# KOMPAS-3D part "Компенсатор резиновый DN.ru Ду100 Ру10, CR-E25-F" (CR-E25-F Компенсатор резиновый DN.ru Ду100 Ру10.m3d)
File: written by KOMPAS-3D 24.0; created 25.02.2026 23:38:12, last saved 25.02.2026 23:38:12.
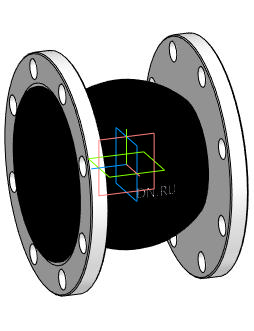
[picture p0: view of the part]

Document properties: Автор: DN.RU; Полное имя файла: D:\PROJECT CAD\DN.RU\...178(4)(ACTUALE). CR-E25-F Компенсатор резиновый DN.ru Ру10-16\DN100_PN10\CR-E25-F Компенсатор резиновый DN.ru Ду100 Ру10.m3d

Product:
- Body: Твердое тело2  | qty 1
    Масса: 11.528562
- Part/product: Компенсатор резиновый DN.ru Ду100 Ру10  | designation CR-E25-F
    Масса: 7.88
    Раздел спецификации: Прочие изделия
    Комментарий: D140-02165
    Примечание: D140-02165
    additional columns: Типовые

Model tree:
1. Твердое тело2  (labels: Твердое тело2)

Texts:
  CR-E25-F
